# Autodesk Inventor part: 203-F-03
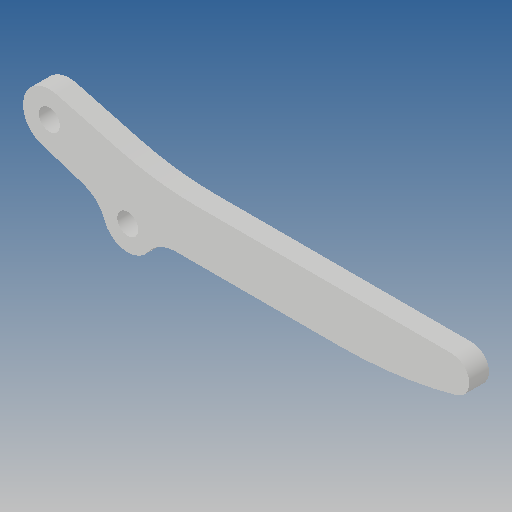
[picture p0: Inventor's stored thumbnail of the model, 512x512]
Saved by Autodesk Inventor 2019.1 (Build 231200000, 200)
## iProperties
Created: 2012-09
Part Number: 203-F-03
Material: Ogólny
Document SubType Name: Modeling
Designer: CADENGINEERING4
Density: 1 g/cm^3
Appearance: Domyślna
Author: CADENGINEERING4
Revision Number: ÈÎºÎ
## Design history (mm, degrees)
feature "Í¹Ì¨-À­Éì1"
node "Bryła1"
